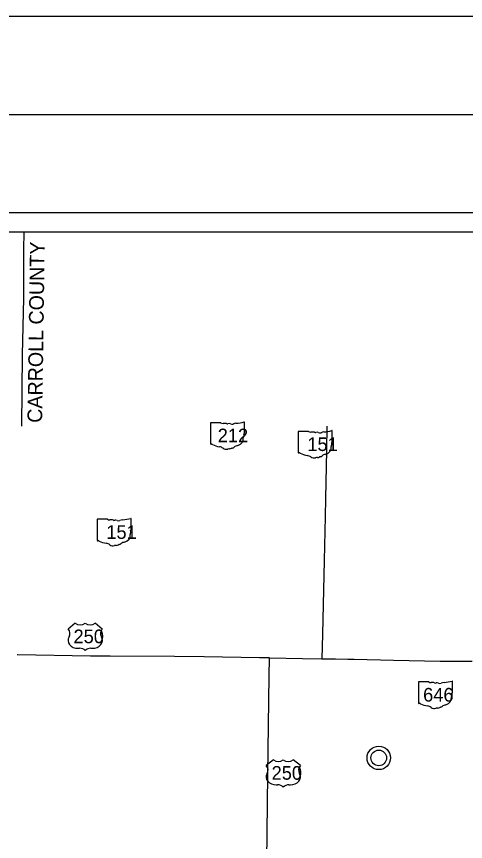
# Model space of a CAD drawing. Extents: x 0 to 70.6, y 0 to 31.9.
# Drawn here: x 3.115 to 5.407, y 17.788 to 22 of the extents above; entities that cross this region are included whole.
import ezdxf

# ---------------------------------------------------------------- set-up
doc = ezdxf.new("R2010")
doc.units = 0
for name, color, linetype in [('GM_X_Adjacent_County', 7, 'Continuous'), ('GM_X_County', 7, 'Continuous'), ('GM_X_County_Road_Text', 7, 'Continuous'), ('GM_X_County_ROW', 7, 'Continuous'), ('GM_X_Minor_Lake_Text', 7, 'Continuous'), ('GM_X_Minor_River', 7, 'Continuous'), ('GM_X_Minor_River_Text', 7, 'Continuous'), ('GM_X_Section', 7, 'Continuous'), ('GM_X_Township', 7, 'Continuous')]:
    doc.layers.add(name, color=color, linetype=linetype)

msp = doc.modelspace()

# ---------------------------------------------------------------- linework, layer by layer
at = {"layer": 'GM_X_Adjacent_County'}
for radius in [0.06, 0.04]:
    msp.add_circle((4.964, 18.2149), radius, dxfattribs=at)
at = {"layer": 'GM_X_County'}
msp.add_lwpolyline([(1.5, 21.5), (33.5, 21.5), (33.5, 0.5), (1.5, 0.5)], close=True, dxfattribs=at)
at = {"layer": 'GM_X_County_Road_Text'}
msp.add_lwpolyline([(3.1515, 20.9), (3.1507, 20.809), (3.1503, 20.6969), (3.1499, 20.5626), (3.1443, 20.2728), (3.1402, 19.909)], dxfattribs=at)
at = {"layer": 'GM_X_County_ROW'}
for points in [[(4.6995, 19.9083), (4.6979, 19.7856), (4.6917, 19.5388), (4.6898, 19.4465), (4.685, 19.2219), (4.6765, 18.847), (4.6738, 18.7214)], [(4.4068, 18.7252), (4.3552, 18.7259), (4.0731, 18.7306), (3.921, 18.7333), (3.5921, 18.7345), (3.5409, 18.7344), (3.4931, 18.7351), (3.1202, 18.7404), (3.1184, 18.7405)], [(4.3922, 17.686), (4.3981, 18.1307), (4.405, 18.6324), (4.4068, 18.7252), (4.5752, 18.7228), (4.6738, 18.7214), (4.7436, 18.7202), (4.8067, 18.7189), (4.839, 18.7183), (5.0397, 18.7143), (5.277, 18.7096), (5.3393, 18.7088), (5.4404, 18.7084)]]:
    msp.add_lwpolyline(points, dxfattribs=at)
at = {"layer": 'GM_X_Minor_Lake_Text'}
for p, q in [((3.4148, 18.902), (3.3786, 18.873)), ((3.5526, 18.873), (3.5163, 18.902)), ((3.4293, 18.7744), (3.4366, 18.7744)), ((3.4946, 18.7744), (3.5018, 18.7744)), ((4.4259, 18.205), (4.3897, 18.176)), ((4.5637, 18.176), (4.5275, 18.205)), ((4.4404, 18.0774), (4.4477, 18.0774)), ((4.5057, 18.0774), (4.5129, 18.0774))]:
    msp.add_line(p, q, dxfattribs=at)
for centre, major_axis, start_param, end_param in [((3.337, 18.8497), (0.0508, 0), 5.838949, 6.894067), ((3.4402, 18.9227), (-0.0363, 0), 0.795399, 2.346194), ((3.491, 18.9227), (-0.0363, 0), 0.795399, 2.346194), ((3.5942, 18.8497), (-0.0508, 0), 5.672304, 6.727422), ((3.4288, 18.815), (0.0508, 0), 2.702327, 4.723529), ((3.5024, 18.815), (-0.0508, 0), 1.559657, 3.580859), ((3.4366, 18.7454), (-0.0363, 0), 3.785094, 4.712389), ((3.4946, 18.7454), (-0.0363, 0), 4.712389, 5.639684), ((4.4513, 18.2257), (-0.0363, 0), 0.795399, 2.346194), ((4.5021, 18.2257), (-0.0363, 0), 0.795399, 2.346194), ((4.3481, 18.1527), (0.0508, 0), 5.838949, 6.894067), ((4.6053, 18.1527), (-0.0508, 0), 5.672304, 6.727422), ((4.4399, 18.118), (0.0508, 0), 2.702327, 4.723529), ((4.5135, 18.118), (-0.0508, 0), 1.559657, 3.580859), ((4.4477, 18.0484), (-0.0363, 0), 3.785094, 4.712389), ((4.5057, 18.0484), (-0.0363, 0), 4.712389, 5.639684)]:
    msp.add_ellipse(centre, major_axis=major_axis, ratio=0.8, start_param=start_param, end_param=end_param, dxfattribs=at)
at = {"layer": 'GM_X_Minor_River_Text'}
for p, q in [((4.1042, 19.9244), (4.1042, 19.8187)), ((4.1569, 19.9262), (4.1059, 19.9262)), ((4.2783, 19.8735), (4.2783, 19.9288)), ((4.6053, 19.8817), (4.5543, 19.8817)), ((4.7266, 19.8291), (4.7266, 19.8843)), ((4.2782, 19.8735), (4.2783, 19.8735)), ((4.5526, 19.8799), (4.5526, 19.7742)), ((4.7266, 19.8291), (4.7266, 19.8291)), ((3.5263, 19.4313), (3.5263, 19.3257)), ((3.579, 19.4331), (3.528, 19.4331)), ((3.7003, 19.3805), (3.7003, 19.4358)), ((3.7003, 19.3805), (3.7003, 19.3805)), ((5.1664, 18.6008), (5.1664, 18.4952)), ((5.2191, 18.6027), (5.1681, 18.6027)), ((5.3404, 18.55), (5.3404, 18.6053)), ((5.3404, 18.55), (5.3404, 18.55))]:
    msp.add_line(p, q, dxfattribs=at)
for centre, major_axis, start_param, end_param in [((4.1062, 19.9246), (0.00202, 0), 1.712693, 3.28349), ((4.169, 19.9384), (0.0196, 0), 4.042523, 4.731795), ((4.1755, 19.8668), (0.0702, 0), 1.404758, 1.657858), ((4.1915, 19.9251), (0.00564, 0), 3.836095, 5.185415), ((4.1997, 19.9129), (0.0117, 0), 0.950623, 2.079405), ((4.2398, 19.8939), (0.0371, 0), 1.699011, 2.107814), ((4.2163, 20.0702), (0.1845, 0), 4.814394, 5.042369), ((4.2763, 19.929), (0.00194, 0), 6.141152, 7.989035), ((4.2149, 19.9297), (0.0141, 0), 4.081561, 5.145723), ((4.5546, 19.8801), (0.00202, 0), 1.712693, 3.28349), ((4.6174, 19.894), (0.0196, 0), 4.042523, 4.731795), ((4.6646, 20.0258), (0.1845, 0), 4.814394, 5.042369), ((4.7247, 19.8846), (0.00194, 0), 6.141152, 7.989035), ((4.2266, 19.8434), (0.0462, 0), 5.101752, 6.440018), ((4.2852, 19.8504), (0.0131, 0), 2.387724, 3.262537), ((4.2778, 19.8695), (0.003, 0), 1.883978, 3.671073), ((4.2587, 19.8625), (0.018, 0), 5.934695, 6.695948), ((4.2762, 19.8733), (0.00207, 0), 5.05454, 6.418171), ((4.6239, 19.8224), (0.0702, 0), 1.404758, 1.657858), ((4.6398, 19.8807), (0.00564, 0), 3.836095, 5.185415), ((4.6481, 19.8685), (0.0117, 0), 0.950623, 2.079405), ((4.6632, 19.8852), (0.0141, 0), 4.081561, 5.145723), ((4.6882, 19.8495), (0.0371, 0), 1.699011, 2.107814), ((4.1062, 19.8185), (0.00203, 0), 3.00124, 4.508301), ((4.1066, 19.8293), (0.0155, 0), 4.665946, 4.897461), ((4.1097, 19.8126), (0.0056, 0), 0.519207, 1.627899), ((4.1804, 19.9075), (0.1333, 0), 4.195997, 4.488961), ((4.1407, 19.7712), (0.0417, 0), 0.823519, 1.323587), ((4.203, 19.8042), (0.0141, 0), 4.691044, 5.507374), ((4.2157, 19.7939), (0.00397, 0), 1.147584, 2.315152), ((4.214, 19.8084), (0.0149, 0), 4.937069, 5.64225), ((4.2461, 19.789), (0.0253, 0), 1.647645, 2.488434), ((4.675, 19.7989), (0.0462, 0), 5.101752, 6.440018), ((4.7336, 19.8059), (0.0131, 0), 2.387724, 3.262537), ((4.7262, 19.825), (0.003, 0), 1.883978, 3.671073), ((4.7071, 19.818), (0.018, 0), 5.934695, 6.695948), ((4.7245, 19.8289), (0.00207, 0), 5.05454, 6.418171), ((4.1858, 19.8121), (0.0265, 0), 4.026481, 4.996735), ((4.201, 19.7755), (0.0217, 0), 1.495662, 1.94098), ((4.5546, 19.774), (0.00203, 0), 3.00124, 4.508301), ((4.5549, 19.7848), (0.0155, 0), 4.665946, 4.897461), ((4.5581, 19.7682), (0.0056, 0), 0.519207, 1.627899), ((4.6287, 19.8631), (0.1333, 0), 4.195997, 4.488961), ((4.589, 19.7268), (0.0417, 0), 0.823519, 1.323587), ((4.6624, 19.764), (0.0149, 0), 4.937069, 5.64225), ((4.6944, 19.7446), (0.0253, 0), 1.647645, 2.488434), ((4.6341, 19.7676), (0.0265, 0), 4.026481, 4.996735), ((4.6494, 19.7311), (0.0217, 0), 1.495662, 1.94098), ((4.6513, 19.7597), (0.0141, 0), 4.691044, 5.507374), ((4.6641, 19.7495), (0.00397, 0), 1.147584, 2.315152), ((3.5283, 19.4316), (0.00202, 0), 1.712693, 3.28349), ((3.5911, 19.4454), (0.0196, 0), 4.042523, 4.731795), ((3.5976, 19.3738), (0.0702, 0), 1.404758, 1.657858), ((3.6135, 19.4321), (0.00564, 0), 3.836095, 5.185415), ((3.6218, 19.4199), (0.0117, 0), 0.950623, 2.079405), ((3.6369, 19.4366), (0.0141, 0), 4.081561, 5.145723), ((3.6619, 19.4009), (0.0371, 0), 1.699011, 2.107814), ((3.6383, 19.5772), (0.1845, 0), 4.814394, 5.042369), ((3.6984, 19.436), (0.00194, 0), 6.141152, 7.989035), ((3.6999, 19.3764), (0.003, 0), 1.883978, 3.671073), ((3.6808, 19.3694), (0.018, 0), 5.934695, 6.695948), ((3.6982, 19.3803), (0.00207, 0), 5.05454, 6.418171), ((3.6487, 19.3503), (0.0462, 0), 5.101752, 6.440018), ((3.7073, 19.3574), (0.0131, 0), 2.387724, 3.262537), ((3.5283, 19.3254), (0.00203, 0), 3.00124, 4.508301), ((3.5286, 19.3362), (0.0155, 0), 4.665946, 4.897461), ((3.5318, 19.3196), (0.0056, 0), 0.519207, 1.627899), ((3.6024, 19.4145), (0.1333, 0), 4.195997, 4.488961), ((3.5627, 19.2782), (0.0417, 0), 0.823519, 1.323587), ((3.6078, 19.319), (0.0265, 0), 4.026481, 4.996735), ((3.6231, 19.2825), (0.0217, 0), 1.495662, 1.94098), ((3.625, 19.3111), (0.0141, 0), 4.691044, 5.507374), ((3.6378, 19.3009), (0.00397, 0), 1.147584, 2.315152), ((3.6361, 19.3154), (0.0149, 0), 4.937069, 5.64225), ((3.6681, 19.296), (0.0253, 0), 1.647645, 2.488434), ((5.1684, 18.6011), (0.00202, 0), 1.712693, 3.28349), ((5.2312, 18.6149), (0.0196, 0), 4.042523, 4.731795), ((5.2377, 18.5433), (0.0702, 0), 1.404758, 1.657858), ((5.2536, 18.6016), (0.00564, 0), 3.836095, 5.185415), ((5.2619, 18.5894), (0.0117, 0), 0.950623, 2.079405), ((5.277, 18.6061), (0.0141, 0), 4.081561, 5.145723), ((5.302, 18.5704), (0.0371, 0), 1.699011, 2.107814), ((5.2784, 18.7467), (0.1845, 0), 4.814394, 5.042369), ((5.3385, 18.6055), (0.00194, 0), 6.141152, 7.989035), ((5.3473, 18.5269), (0.0131, 0), 2.387724, 3.262537), ((5.34, 18.5459), (0.003, 0), 1.883978, 3.671073), ((5.3209, 18.539), (0.018, 0), 5.934695, 6.695948), ((5.3383, 18.5498), (0.00207, 0), 5.05454, 6.418171), ((5.1684, 18.4949), (0.00203, 0), 3.00124, 4.508301), ((5.1687, 18.5057), (0.0155, 0), 4.665946, 4.897461), ((5.1719, 18.4891), (0.0056, 0), 0.519207, 1.627899), ((5.2425, 18.584), (0.1333, 0), 4.195997, 4.488961), ((5.2888, 18.5198), (0.0462, 0), 5.101752, 6.440018), ((5.2028, 18.4477), (0.0417, 0), 0.823519, 1.323587), ((5.2479, 18.4885), (0.0265, 0), 4.026481, 4.996735), ((5.2632, 18.452), (0.0217, 0), 1.495662, 1.94098), ((5.2651, 18.4806), (0.0141, 0), 4.691044, 5.507374), ((5.2779, 18.4704), (0.00397, 0), 1.147584, 2.315152), ((5.2762, 18.4849), (0.0149, 0), 4.937069, 5.64225), ((5.3082, 18.4655), (0.0253, 0), 1.647645, 2.488434)]:
    msp.add_ellipse(centre, major_axis=major_axis, ratio=0.8, start_param=start_param, end_param=end_param, dxfattribs=at)
at = {"layer": 'GM_X_Section'}
msp.add_lwpolyline([(0, 0), (34, 0), (34, 22), (0, 22)], close=True, dxfattribs=at)
at = {"layer": 'GM_X_Township'}
for p, q in [((2, 21), (9, 21)), ((2.1, 20.9), (8.9, 20.9))]:
    msp.add_line(p, q, dxfattribs=at)

# ---------------------------------------------------------------- texts
at = {"layer": 'GM_X_Minor_Lake_Text'}
for p in [(3.4057, 18.8005), (4.4169, 18.1035)]:
    msp.add_text('250', height=0.06961, dxfattribs=at).set_placement(p)
at = {"layer": 'GM_X_Minor_River'}
msp.add_text('CARROLL COUNTY', height=0.075, rotation=89.1612, dxfattribs=at).set_placement((3.2454, 19.9252))
at = {"layer": 'GM_X_Minor_River_Text'}
for s, p in [('212', (4.1418, 19.8261)), ('151', (4.5995, 19.7817)), ('151', (3.5732, 19.3331)), ('646', (5.1904, 18.5026))]:
    msp.add_text(s, height=0.06961, dxfattribs=at).set_placement(p)

doc.saveas('drawing.dxf')
